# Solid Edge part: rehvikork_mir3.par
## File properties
Author: KULL
Template: Iso Metric Part.par
Last saved by: KULL
Revision: 2
Application: Solid Edge
Accuracy: 0,990
Username: KULL
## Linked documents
rehvikork.par
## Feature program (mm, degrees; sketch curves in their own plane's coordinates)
part copy "CopiedPart_1"
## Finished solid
Body 1: solid body, 93 faces, 217 edges, 128 vertices.
  Faces by surface: blend 40, spline 40, sphere 6, torus 3, cylinder 2, cone 1, plane 1
  Edges by curve: intersection 128, circle 49, line 40
Bounding box of the edges (mm; curved faces can reach further): 4.951 x 16.000 x 16.000, from (-4, -8, -8) to (0.951, 8, 8).
Cylindrical faces by radius (mm): R7 x1, R8 x1
Conical faces (half-angle, radius in mm at the cone's reference point): 11.8765 deg R7 x1
Toroidal faces (ring radius, tube radius in mm): R7.0618 r0.08 x1, R7.6 r0.4 x1, R7.92 r0.08 x1
Spherical faces by radius (mm): R33.0132 x1, R33.5132 x2, R34.0132 x3
Planar faces by outward normal: -x 1
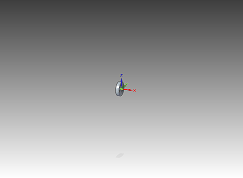
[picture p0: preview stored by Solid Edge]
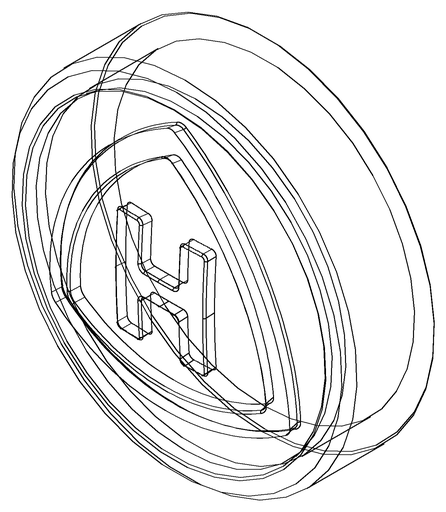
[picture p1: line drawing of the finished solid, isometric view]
